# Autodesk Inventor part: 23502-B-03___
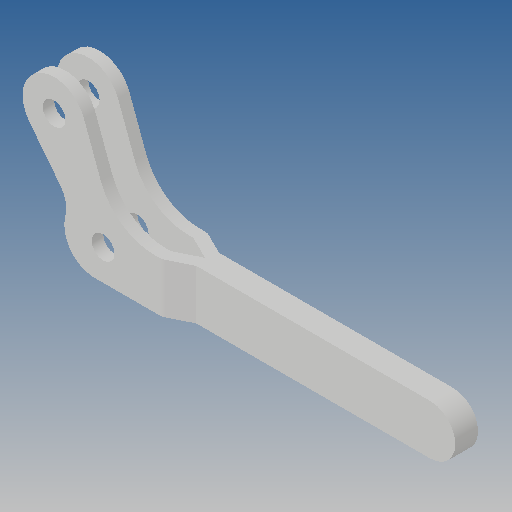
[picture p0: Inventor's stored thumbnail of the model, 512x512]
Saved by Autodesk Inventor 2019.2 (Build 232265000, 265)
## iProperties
Created: 2010-06
Part Number: 23502-B-03___
Material: Ogólny
Document SubType Name: Modeling
Designer: CADENGINEERING4
Density: 1 g/cm^3
Appearance: Domyślna
Author: CADENGINEERING4
Revision Number: ANY
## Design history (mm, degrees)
feature "NONE"
node "Bryła1"
